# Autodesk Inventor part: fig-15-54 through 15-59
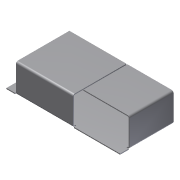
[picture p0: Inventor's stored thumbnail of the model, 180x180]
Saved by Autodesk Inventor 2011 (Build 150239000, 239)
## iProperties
Created: 2008-06
Part Number: fig-15-54 through 15-59
Material: Default
Document SubType Name: Sheet Metal
Designer: CADCIM
Density: 1 g/cm^3
Sheet Metal Rule: Default_mm
Author: CADCIM
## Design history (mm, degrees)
node "Face1"
  sketch "Sketch1"
    geometry: L1 (-32.219, 28.184)-(27.554, 28.184); L2 (27.554, 28.184)-(27.554, 0.063); L3 (27.554, 0.063)-(-32.219, 0.063); L4 (-32.219, 0.063)-(-32.219, 28.184)
    constraints: 8 end point, 2 parallel, 1 horizontal, 1 perpendicular
node "Flange1"
node "Flange2"
node "Flange3"
node "Flange4"
feature "Corner5" dims "d45" = 2 (= CornerReliefSize), "d46" = 0.5 (= BendRadius), "d47" = 0.5 (= Thickness), "d48" = 0, "d49" = 10, "Thickness" = 0.5
body "Solid1"
face "Plate1" dims "Thickness" = 0.5
sketch "Sketch2"
  geometry: L1 (-54.773, 0)-(-24.773, 0); L2 (-24.773, 0)-(-24.773, 15); L3 (-24.773, 15)-(-54.773, 15); L4 (-54.773, 15)-(-54.773, 0)
  constraints: 8 end point
face "Plate2" dims "d1" = 0.5 (= BendReliefWidth), "d2" = 0.25 (= BendReliefDepth), "d3" = 1 (= MinimumRemnant), "d4" = 0.5 (= BendRadius), "d5" = 30, "d6" = 5, "d7" = 15, "d8" = 90 deg, "d9" = 0.5 (= BendRadius), "d10" = 2 (= CornerReliefSize), "d11" = 0.5 (= Thickness), "d12" = 0.5 (= JacobiRadiusSize), "SeamGap" = 0.01, "Thickness" = 0.5
bend "Bend1" dims "d1" = 0.5 (= BendReliefWidth), "d2" = 0.25 (= BendReliefDepth), "d3" = 1 (= MinimumRemnant), "d4" = 0.5 (= BendRadius), "d7" = 15, "d8" = 90 deg, "d9" = 0.5 (= BendRadius), "SeamGap" = 0.01, "Thickness" = 0.5
feature "Corner1" dims "d7" = 15, "d8" = 90 deg, "d10" = 2 (= CornerReliefSize), "d11" = 0.5 (= Thickness), "d12" = 0.5 (= JacobiRadiusSize)
sketch "Sketch3"
  geometry: L1 (0, 15)-(-23.121, 15); L2 (-23.121, 15)-(-23.121, 0); 2 other entities
  constraints: 4 end point, 4 other
face "Plate3" dims "d13" = 0.5 (= BendReliefWidth), "d14" = 0.25 (= BendReliefDepth), "d15" = 1 (= MinimumRemnant), "d16" = 0.5 (= BendRadius), "d17" = 0, "d18" = 5, "d19" = 15, "d20" = 90 deg, "d21" = 0.5 (= BendRadius), "d22" = 2 (= CornerReliefSize), "d23" = 0.5 (= Thickness), "d24" = 0.5 (= JacobiRadiusSize), "SeamGap" = 0.01, "Thickness" = 0.5
bend "Bend2" dims "d13" = 0.5 (= BendReliefWidth), "d14" = 0.25 (= BendReliefDepth), "d15" = 1 (= MinimumRemnant), "d16" = 0.5 (= BendRadius), "d19" = 15, "d20" = 90 deg, "d21" = 0.5 (= BendRadius), "SeamGap" = 0.01, "Thickness" = 0.5
feature "Corner2" dims "d19" = 15, "d20" = 90 deg, "d22" = 2 (= CornerReliefSize), "d23" = 0.5 (= Thickness), "d24" = 0.5 (= JacobiRadiusSize)
sketch "Sketch4"
  geometry: L1 (0, 15)-(-30, 15); L2 (-30, 15)-(-30, 0); 2 other entities
  constraints: 4 end point, 4 other
face "Plate4" dims "d25" = 0.5 (= BendReliefWidth), "d26" = 0.25 (= BendReliefDepth), "d27" = 1 (= MinimumRemnant), "d28" = 0.5 (= BendRadius), "d29" = 15, "d30" = 90 deg, "d31" = 0.5 (= BendRadius), "d32" = 2 (= CornerReliefSize), "d33" = 0.5 (= Thickness), "d34" = 0.5 (= JacobiRadiusSize), "SeamGap" = 0.01, "Thickness" = 0.5
bend "Bend3" dims "d25" = 0.5 (= BendReliefWidth), "d26" = 0.25 (= BendReliefDepth), "d27" = 1 (= MinimumRemnant), "d28" = 0.5 (= BendRadius), "d29" = 15, "d30" = 90 deg, "d31" = 0.5 (= BendRadius), "SeamGap" = 0.01, "Thickness" = 0.5
feature "Corner3" dims "d29" = 15, "d30" = 90 deg, "d32" = 2 (= CornerReliefSize), "d33" = 0.5 (= Thickness), "d34" = 0.5 (= JacobiRadiusSize)
sketch "Sketch5"
  geometry: L1 (15, 0)-(15, 23.121); L2 (15, 23.121)-(0, 23.121); 2 other entities
  constraints: 4 end point, 4 other
face "Plate5" dims "d35" = 0.5 (= BendReliefWidth), "d36" = 0.25 (= BendReliefDepth), "d37" = 1 (= MinimumRemnant), "d38" = 0.5 (= BendRadius), "d39" = 15, "d40" = 90 deg, "d41" = 0.5 (= BendRadius), "d42" = 2 (= CornerReliefSize), "d43" = 0.5 (= Thickness), "d44" = 0.5 (= JacobiRadiusSize), "SeamGap" = 0.01, "Thickness" = 0.5
bend "Bend4" dims "d35" = 0.5 (= BendReliefWidth), "d36" = 0.25 (= BendReliefDepth), "d37" = 1 (= MinimumRemnant), "d38" = 0.5 (= BendRadius), "d39" = 15, "d40" = 90 deg, "d41" = 0.5 (= BendRadius), "SeamGap" = 0.01, "Thickness" = 0.5
feature "Corner4" dims "d39" = 15, "d40" = 90 deg, "d42" = 2 (= CornerReliefSize), "d43" = 0.5 (= Thickness), "d44" = 0.5 (= JacobiRadiusSize)
other parameters: "BendRadius" = 0.5 (= Thickness), "BendReliefWidth" = 0.5 (= Thickness), "BendReliefDepth" = 0.25 (= 0.5 x Thickness), "CornerReliefSize" = 2 (= 4 x Thickness), "MinimumRemnant" = 1 (= 2 x Thickness), "TransitionRadius" = 0.5 (= BendRadius), "JacobiRadiusSize" = 0.5 (= BendRadius), "d0" = 0.5 (= BendRadius), "GapSize" = 0.5 (= Thickness)
